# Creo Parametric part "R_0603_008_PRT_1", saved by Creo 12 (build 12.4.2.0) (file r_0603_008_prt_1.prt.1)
Units: Custom; MM, KILOGRAM, SECS

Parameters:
  PTC_WM_ITERATION = "0"
  PTC_WM_VERSION = "-.0"
  PTC_WM_LIFECYCLE_STATE = "In Work"
  PTC_WM_LIFECYCLE = "MO_CADDocument"
  PTC_WM_CREATED_BY = "Maximilian Roepper (Z0017RMS: MO)"
  PTC_WM_CREATED_ON = "18-Sep-26 11:36:42 AM"
  PTC_WM_MODIFIED_BY = "Maximilian Roepper (Z0017RMS: MO)"
  PTC_WM_MODIFIED_ON = "18-Sep-26 11:36:46 AM"
  PDMLINKNUMBER = "PDM000071455245"
  PTC_WM_NAME = "r_0603_008_prt_1.prt"
  PTC_WM_NUMBER = "PDM000071455245"

Other parameters: WEIGHT, WEIGHT_FACTOR, WEIGHT_ADD, _MASS_TEMP, _DIFF_TEMP, MC_ERRORS, SUPPLIER

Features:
  1. coordinate system
  2. datum plane "PRT_YZ"
  3. datum plane "PRT_XY"
  4. datum plane "PRT_XZ"
  5. coordinate system
  6. datum axis
  7. datum axis
  8. datum axis
  9. coordinate system
  10. imported feature
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
Other named items: PRT, SIEMENS_MO, DRW_VIEW_ORG, PRT_X, PRT_Y, PRT_Z, CS0, ROUGH_GROB

Layers: 00_STD_CSYS-KSYS, 01_STD_PLANES-EBENEN, 02_STD_AXES-ACHSEN, 03_STD_CSYS-KSYS, 24_IMPORT_FEAT-IMPORT_KE

Surfaces: 18 plane, 8 cylinder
